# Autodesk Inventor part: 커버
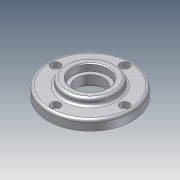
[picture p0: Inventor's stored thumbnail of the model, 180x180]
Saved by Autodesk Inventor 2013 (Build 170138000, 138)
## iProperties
Company: 한국ATC센터
Created: 2013-01
Part Number: 커버
Document SubType Name: Modeling
Designer: KYOUNG IL JANG
Density: 1 g/cm^3
Material: 일반
Author: KYOUNG IL JANG
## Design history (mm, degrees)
sketch "스케치1"
  geometry: C1 r 31 at (0, 0) reference; C2 r 50 at (0, 0); 1 further point
  constraints: 1 centre point, 1 coincident
  dimensions: "d41" = 100 diameter of C2
extrude "돌출1" new body sketch "스케치1" distance "d0" = 12; taper "d1" = 0 deg
sketch "스케치2"
  geometry: C1 r 30 at (0, 0); 1 further point
  constraints: 1 centre point, 1 coincident
  dimensions: "d2" = 60 diameter of C1
extrude "돌출2" join sketch "스케치2" distance "d3" = 8; taper "d4" = 0 deg
fillet "모깎기1" dims "d5" = 3
sketch "스케치3" dims "d42" = 82
  geometry: 3 further points
  constraints: 2 vertical alignment, 1 coincident, 2 other
hole "구멍1" sketch "스케치3" at (0, 41) diameter "d6" = 6.6; stored, may be unused: countersink angle "d10" = 90 deg, drill point angle "d12" = 118 deg; dims "d7" = 6, "d8" = 11, "d9" = 6.5, "d11" = 8
hole "구멍2" diameter "d18" = 33; stored, may be unused: countersink angle "d22" = 90 deg, drill point angle "d24" = 118 deg; dims "d16" = 10, "d17" = 10, "d19" = 6, "d20" = 42, "d21" = 8.5, "d23" = 8
sketch "스케치4"
  geometry: C1 r 31 at (0, 0) reference; C2 r 22.5 at (0, 0); 1 further point
  constraints: 1 centre point, 1 coincident
  dimensions: "d43" = 45 diameter of C2
extrude "돌출3" join sketch "스케치4" distance "d25" = 6; taper "d26" = 0 deg
hole "구멍3" diameter "d29" = 50; stored, may be unused: countersink angle "d33" = 90 deg, drill point angle "d35" = 0 deg; dims "d27" = 10, "d28" = 10, "d30" = 6, "d31" = 42, "d32" = 8.5, "d34" = 7
fillet "모깎기2" dims "d36" = 3, "d37" = 0.3
chamfer "모따기1" distance "d38" = 1; stored, may be unused: second distance "d39" = 2, angle "d40" = 45 deg
node "솔리드1"
pattern_circular "원형 패턴1" dims angle "d14" = 360 deg
node "참조9"
node "참조11"
